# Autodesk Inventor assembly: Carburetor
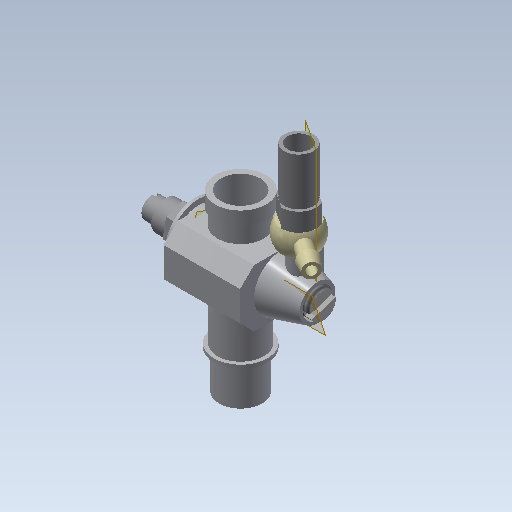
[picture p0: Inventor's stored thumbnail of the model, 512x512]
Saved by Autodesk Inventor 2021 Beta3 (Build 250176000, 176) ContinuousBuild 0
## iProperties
Created: 2012-08
Part Number: Carburetor
Document SubType Name: Assembly
Designer: John
Author: John
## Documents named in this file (8)
- C:\Users\John Helfen\Desktop\Ex_Files_Autodesk_Inventor_2020_EssT\Ex_Files_Autodesk_Inventor_2021_EssT\Exercise Files\03_Navigating the interface\03_01\Carburetor.iam
- C:\Users\John Helfen\Desktop\Ex_Files_Autodesk_Inventor_2020_EssT\Ex_Files_Autodesk_Inventor_2021_EssT\Exercise Files\03_Navigating the interface\03_01\Gas Regulator.ipt
- C:\Users\John Helfen\Desktop\Ex_Files_Autodesk_Inventor_2020_EssT\Ex_Files_Autodesk_Inventor_2021_EssT\Exercise Files\03_Navigating the interface\03_01\Mixture Control.ipt
- C:\Users\John Helfen\Desktop\Ex_Files_Autodesk_Inventor_2020_EssT\Ex_Files_Autodesk_Inventor_2021_EssT\Exercise Files\03_Navigating the interface\03_01\Air Adjuster.ipt
- C:\Users\John Helfen\Desktop\Ex_Files_Autodesk_Inventor_2020_EssT\Ex_Files_Autodesk_Inventor_2021_EssT\Exercise Files\03_Navigating the interface\03_01\Hex Cap.ipt
- C:\Users\John Helfen\Desktop\Ex_Files_Autodesk_Inventor_2020_EssT\Ex_Files_Autodesk_Inventor_2021_EssT\Exercise Files\03_Navigating the interface\03_01\Fuel Intake.ipt
- C:\Users\John Helfen\Desktop\Ex_Files_Autodesk_Inventor_2020_EssT\Ex_Files_Autodesk_Inventor_2021_EssT\Exercise Files\03_Navigating the interface\03_01\Fuel Adjuster.ipt
- C:\Users\John Helfen\Desktop\Ex_Files_Autodesk_Inventor_2020_EssT\Ex_Files_Autodesk_Inventor_2021_EssT\Exercise Files\03_Navigating the interface\03_01\Carburetor Housing_v3.ipt
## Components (7 placed, 7 different names)
1. Carburetor Housing_v3:2 — Mate:6, Mate:7, Mate:10, Flush:1, Flush:2
2. Gas Regulator:1 — Mate:6, Flush:1
3. Mixture Control:1 — Flush:2
4. Air Adjuster:1
5. Hex Cap:1
6. Fuel Intake:1 — Mate:8, Mate:9, Mate:10
7. Fuel Adjuster:1 — Mate:7, Mate:8, Mate:9
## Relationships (7: Mate 5, Flush 2)
- Mate:6: Carburetor Housing_v3:2 ↔ Gas Regulator:1
- Mate:7: Carburetor Housing_v3:2 ↔ Fuel Adjuster:1
- Mate:8: Fuel Intake:1 ↔ Fuel Adjuster:1
- Mate:9: Fuel Intake:1 ↔ Fuel Adjuster:1
- Mate:10: Carburetor Housing_v3:2 ↔ Fuel Intake:1
- Flush:1: Carburetor Housing_v3:2 ↔ Gas Regulator:1
- Flush:2: Carburetor Housing_v3:2 ↔ Mixture Control:1
